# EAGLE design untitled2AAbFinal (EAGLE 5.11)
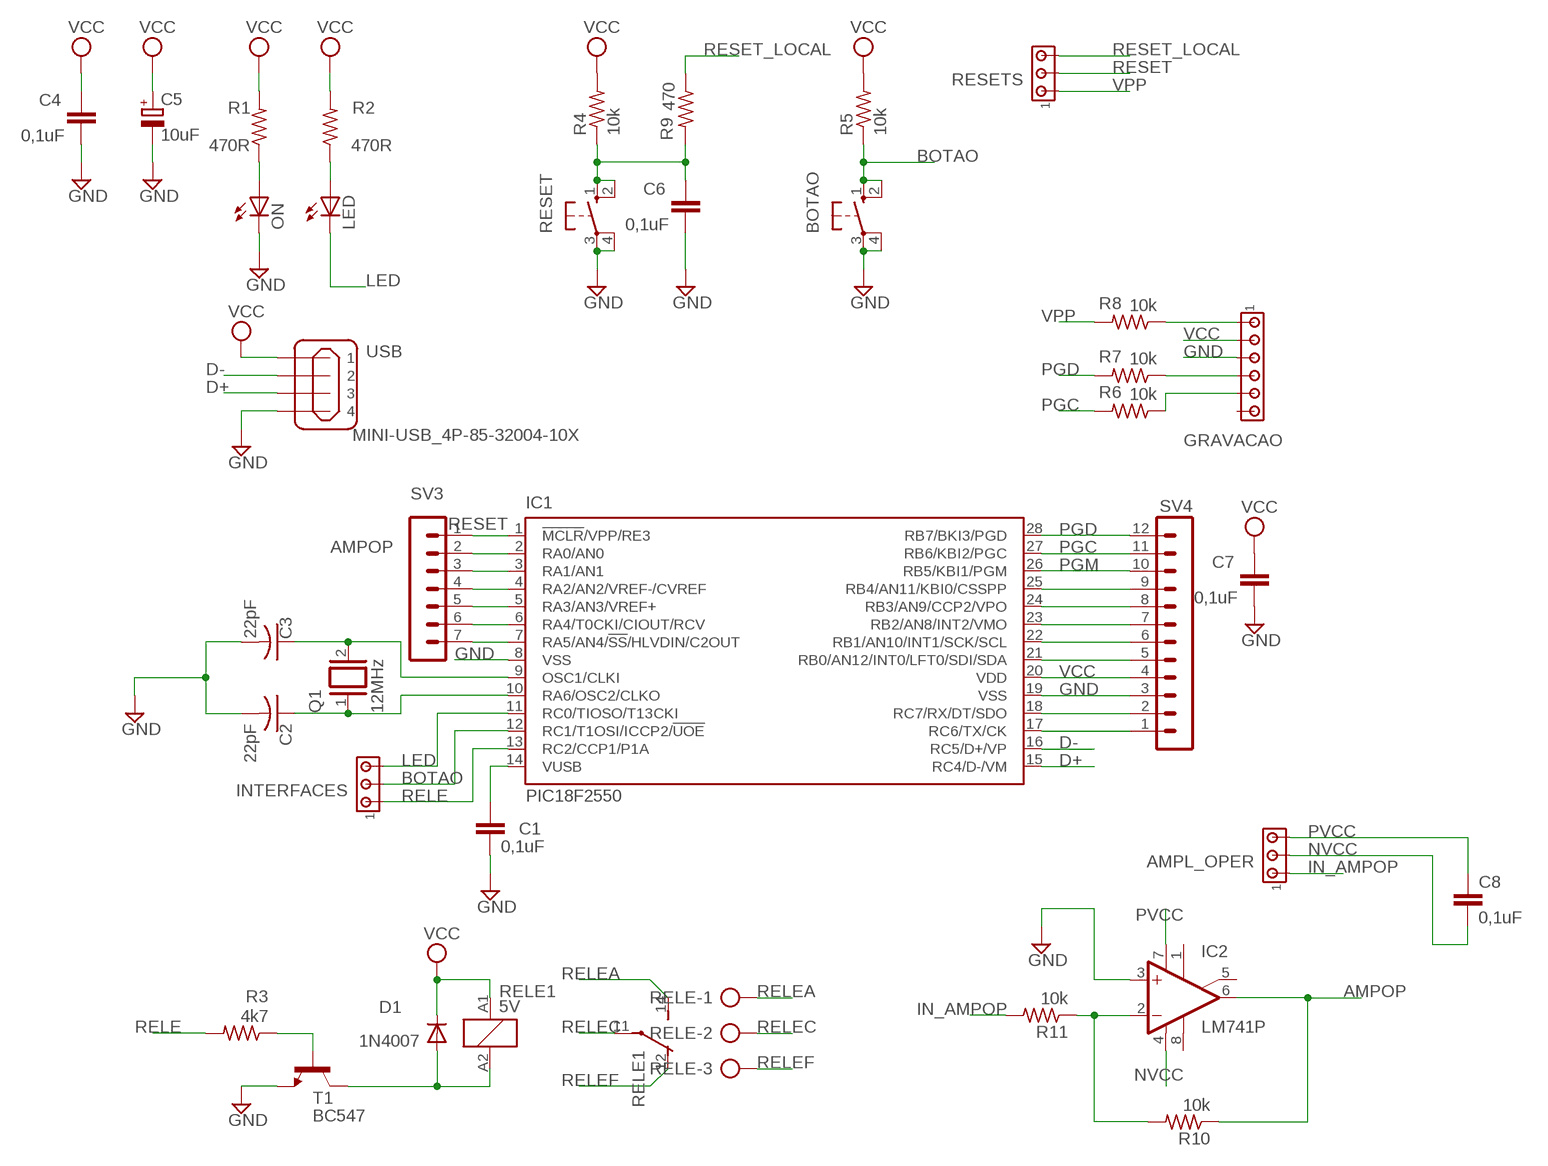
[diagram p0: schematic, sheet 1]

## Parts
AMPL_OPER  MTA03-100  [10X03MTA]
BOTAO  10-XX  [B3F-10XX]
C1  0,1uF  C5/3  [C5B3]
C2  22pF  C-US025-025X050  [C025-025X050]
C3  22pF  C-US025-025X050  [C025-025X050]
C4  0,1uF  C5/3  [C5B3]
C5  10uF  CPOL-EUE5-8.5  [E5-8,5]
C6  0,1uF  C5/3  [C5B3]
C7  0,1uF  C5/3  [C5B3]
C8  0,1uF  C5/3  [C5B3]
D1  1N4007  1N4004  [DO41-10]
GRAVACAO  MTA06-100  [10X06MTA]
IC1  PIC18F2550  PIC18F2550_28DIP  [DIL28-3]
IC2  LM741P  [DIL08]
INTERFACES  MTA03-100  [10X03MTA]
LED  LED5MM  [LED5MM]
ON  LED5MM  [LED5MM]
Q1  12MHz  XTAL/S  [QS]
R1  470R  R-US_0207/10  [0207/10]
R2  470R  R-US_0207/10  [0207/10]
R3  4k7  R-US_0207/10  [0207/10]
R4  10k  R-US_0207/10  [0207/10]
R5  10k  R-US_0207/10  [0207/10]
R6  10k  R-US_0207/10  [0207/10]
R7  10k  R-US_0207/10  [0207/10]
R8  10k  R-US_0207/10  [0207/10]
R9  470  R-US_0207/10  [0207/10]
R10  10k  R-US_0207/10  [0207/10]
R11  10k  R-US_0207/10  [0207/10]
RELE  AK500/3  [AK500/3]
RELE1  5V  ZNS5124  [ZN5]
RESET  10-XX  [B3F-10XX]
RESETS  MTA03-100  [10X03MTA]
SV3  MA07-1  [MA07-1]
SV4  MA12-1  [MA12-1]
T1  BC547  [TO92]
USB  MINI-USB_4P-85-32004-10X  [85-32004-10X]

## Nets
AMPOP: IC1.2(RA0/AN0) IC2.6(OUT) R10.1 SV3.2
BOTAO: BOTAO.1(S) BOTAO.2(S1) IC1.12(RC1/T1OSI/ICCP2/!UOE) INTERFACES.2 R5.1
D+: IC1.15(RC4/D-/VM) USB.3
D-: IC1.16(RC5/D+/VP) USB.2
GND: BOTAO.3(P) BOTAO.4(P1) C1.2 C2.2 C3.2 C4.2 C5.- C6.2 C7.2 GRAVACAO.4 IC1.8(VSS) IC1.19(VSS) IC2.3(+IN) ON.K(C) RESET.3(P) RESET.4(P1) SV4.3 T1.1(E) USB.4
IN_AMPOP: AMPL_OPER.1 R11.2
LED: IC1.11(RC0/TIOSO/T13CKI) INTERFACES.3 LED.K(C)
N$1: C1.1 IC1.14(VUSB)
N$2: D1.A RELE1.A2 T1.3(C)
N$3: LED.A R2.1
N$4: ON.A R1.1
N$5: GRAVACAO.6 R8.1
N$6: IC1.17(RC6/TX/CK) SV4.1
N$7: IC2.2(-IN) R10.2 R11.1
N$8: IC1.18(RC7/RX/DT/SDO) SV4.2
N$9: C3.1 IC1.9(OSC1/CLKI) Q1.2
N$10: C2.1 IC1.10(RA6/OSC2/CLKO) Q1.1
N$12: R3.1 T1.2(B)
N$13: IC1.21(RB0/AN12/INT0/LFT0/SDI/SDA) SV4.5
N$14: IC1.22(RB1/AN10/INT1/SCK/SCL) SV4.6
N$15: IC1.23(RB2/AN8/INT2/VMO) SV4.7
N$16: IC1.24(RB3/AN9/CCP2/VPO) SV4.8
N$17: IC1.25(RB4/AN11/KBI0/CSSPP) SV4.9
N$18: C6.1 R4.1 R9.2 RESET.1(S) RESET.2(S1)
N$19: IC1.3(RA1/AN1) SV3.3
N$20: IC1.4(RA2/AN2/VREF-/CVREF) SV3.4
N$22: IC1.5(RA3/AN3/VREF+) SV3.5
N$23: IC1.6(RA4/T0CKI/CIOUT/RCV) SV3.6
N$24: IC1.7(RA5/AN4/!SS!/HLVDIN/C2OUT) SV3.7
N$25: GRAVACAO.3 R7.1
N$26: GRAVACAO.2 R6.1
NVCC: AMPL_OPER.2 C8.2 IC2.4(V-)
PGC: IC1.27(RB6/KBI2/PGC) R6.2 SV4.11
PGD: IC1.28(RB7/BKI3/PGD) R7.2 SV4.12
PGM: IC1.26(RB5/KBI1/PGM) SV4.10
PVCC: AMPL_OPER.3 C8.1 IC2.7(V+)
RELE: IC1.13(RC2/CCP1/P1A) INTERFACES.1 R3.2
RELEA: RELE1.14(2:S) RELE.1
RELEC: RELE1.11(2:P) RELE.2
RELEF: RELE1.12(2:O) RELE.3
RESET: IC1.1(!MCLR!/VPP/RE3) RESETS.2 SV3.1
RESET_LOCAL: R9.1 RESETS.3
VCC: C4.1 C5.+ C7.1 D1.C GRAVACAO.5 IC1.20(VDD) R1.2 R2.2 R4.2 R5.2 RELE1.A1 SV4.4 USB.1
VPP: R8.2 RESETS.1
Unconnected: GRAVACAO.1 IC2.1(ON1) IC2.5(ON2) IC2.8(OPT)

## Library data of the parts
AMPL_OPER INTERFACES RESETS = con-amp:MTA03-100: AMP connector; OC_FARNELL: unknown; OC_NEWARK: unknown
BOTAO RESET = switch-omron:10-XX: OMRON SWITCH; MPN: B3F-1000; OC_FARNELL: 176432; OC_NEWARK: 36M3542
C1 C4 C6-C8 = capacitor-wima:C: CAPACITOR
C2 C3 = resistor:C-US: CAPACITOR, American symbol
C5 = rcl:CPOL-EU: POLARIZED CAPACITOR, European symbol
D1 = diode:1N4004: DIODE
GRAVACAO = con-amp:MTA06-100: AMP connector; OC_FARNELL: unknown; OC_NEWARK: unknown
IC1 = microchip:PIC18F2*_28: USB Microcontrollers with nanoWatt Technology High-Performance, Enhanced Flash, 28/40/44-Pin, Source: http://ww1.microchip.com/downloads/en/devicedoc/39632c.pdf; MF: MICROCHIP; MPN: PIC18F2550-I/SP; OC_FARNELL: 1523822; OC_NEWARK: 80K6054
IC2 = linear:*741: OP AMP
LED ON = led:LED: LED
Q1 = special:XTAL/S: CRYSTAL
R1-R11 = resistor:R-US_: RESISTOR, American symbol
RELE = con-ptr500:AK500/3: CONNECTOR; OC_FARNELL: unknown; OC_NEWARK: unknown
RELE1 = relay:ZNS5*: Miniature Power PCB Relay SCHRACK 1pole 10 A Source: http://www.schrack.com/.. 5847.pdf; OC_FARNELL: unknown; OC_NEWARK: unknown
SV3 = con-lstb:MA07-1: PIN HEADER; OC_FARNELL: unknown; OC_NEWARK: unknown
SV4 = con-lstb:MA12-1: PIN HEADER; OC_FARNELL: unknown; OC_NEWARK: unknown
T1 = transistor:BC547: NPN TRANSISTOR
USB = con-cypressindustries:MINI-USB_4P-: MINI USB 4 Pol. Source: www.cypressindustries.com; OC_FARNELL: unknown; OC_NEWARK: unknown

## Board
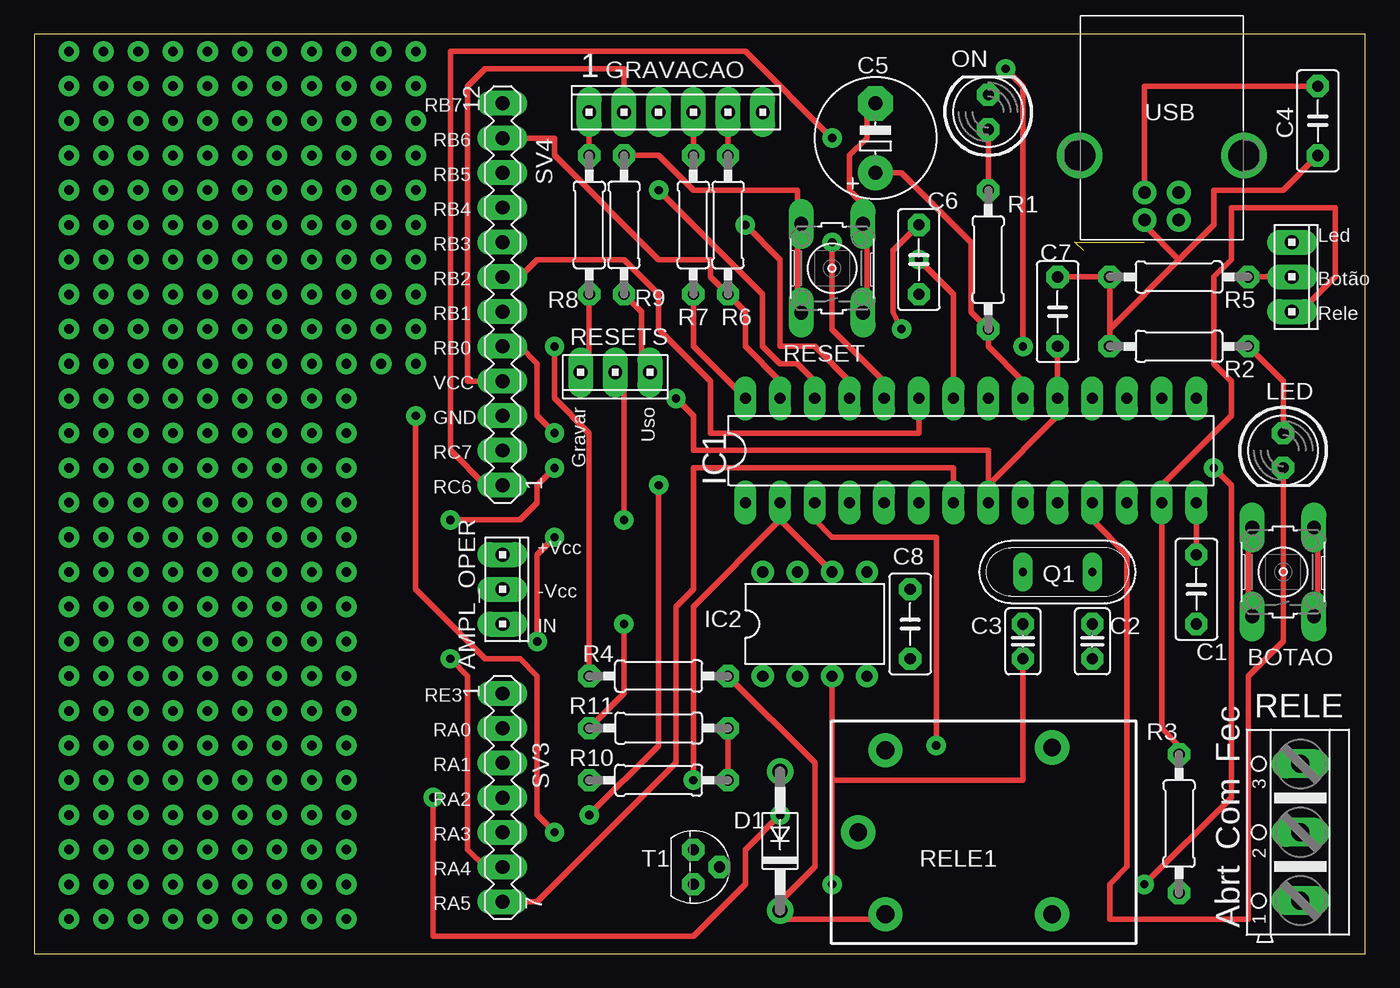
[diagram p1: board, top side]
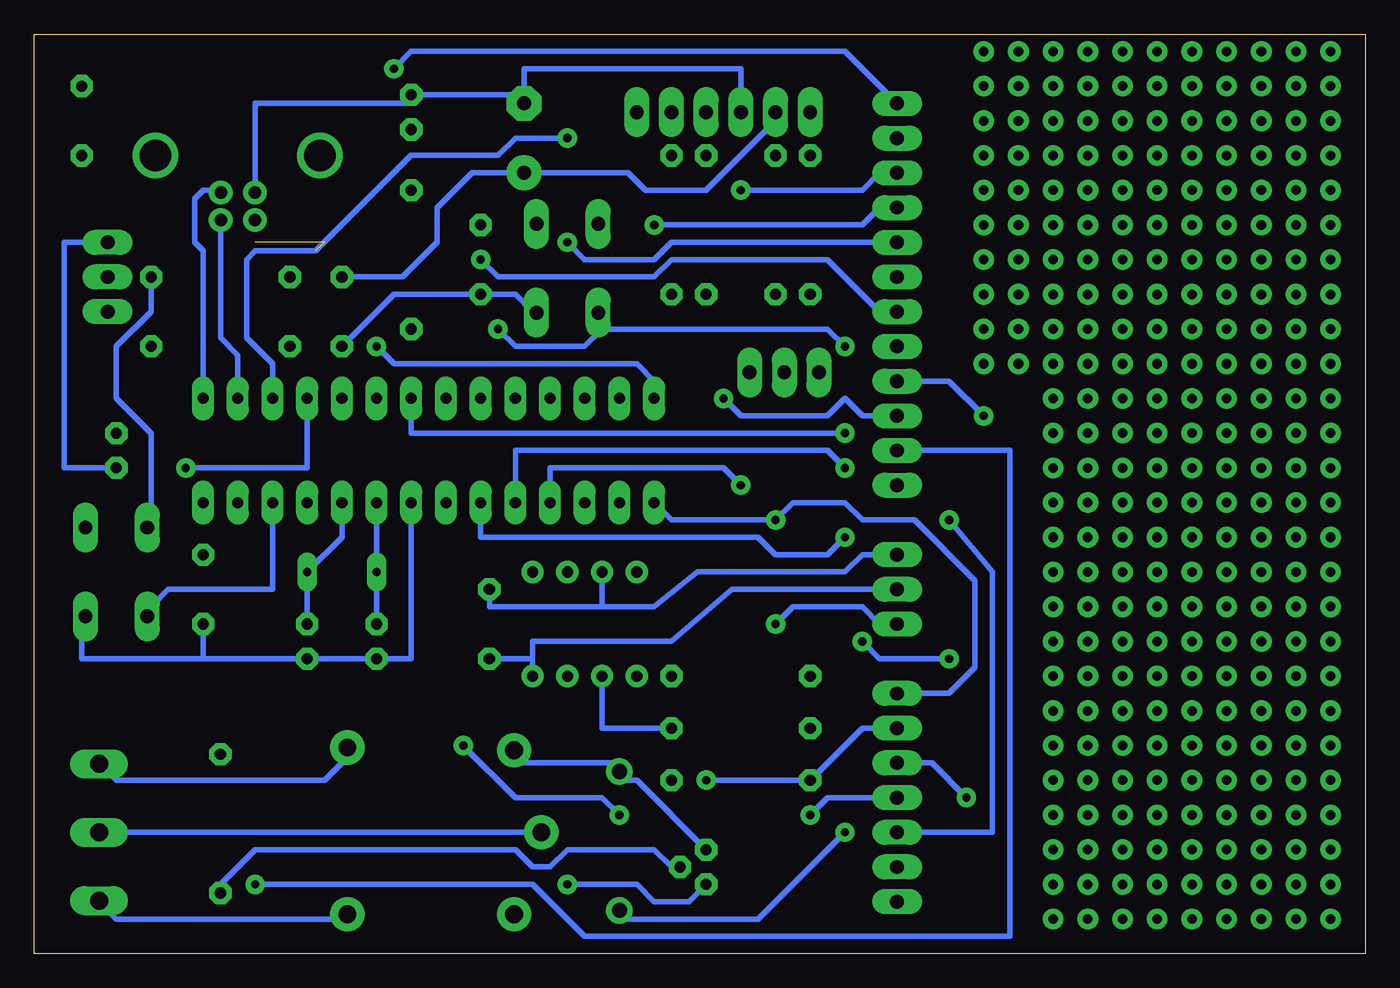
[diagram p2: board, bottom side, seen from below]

Size 97.46 x 67.3 mm. Coordinates in mm from the lower left corner, seen from the top.
Outline: 0,0 97.46,0 97.46,67.3 0,67.3 0,0
Copper layers (1*16): Top 0.035mm / dielectric 1.5mm / Bottom 0.035mm
Design rules "default *": minimum track width 16mil, minimum drill 24mil, track to track 16mil, track to pad 16mil, pad to pad 16mil, via to via 16mil, smd to smd 8mil, copper to edge 40mil, drill to drill 12mil, minimum pad ring 16mil, minimum via ring 16mil, stop-mask expansion 4mil, vias tented up to drill 0mil, thermal gap 10mil

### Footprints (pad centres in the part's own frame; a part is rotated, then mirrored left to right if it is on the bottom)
10X03MTA = drill 1.016 long: 1 2.54,0; 2 0,0; 3 -2.54,0
B3F-10XX = drill 1.016 long: 1 -3.251,2.261; 2 3.251,2.261; 3 -3.251,-2.261; 4 3.251,-2.261
C5B3 = drill 0.813 pad 1.6 octagon: 1 -2.54,0; 2 2.54,0
C025-025X050 = drill 0.813 octagon: 1 -1.27,0; 2 1.27,0
E5-8,5 = drill 1.016 pad 2.54 round: + -2.54,0 | drill 1.016 pad 2.54 octagon: - 2.54,0
DO41-10 = drill 1.118 round: A 5.08,0; C -5.08,0
10X06MTA = drill 1.016 long: 1 6.35,0; 2 3.81,0; 3 1.27,0; 4 -1.27,0; 5 -3.81,0; 6 -6.35,0
DIL28-3 = drill 0.813 long: 1 -16.51,-3.81; 2 -13.97,-3.81; 3 -11.43,-3.81; 4 -8.89,-3.81; 5 -6.35,-3.81; 6 -3.81,-3.81; 7 -1.27,-3.81; 8 1.27,-3.81; 9 3.81,-3.81; 10 6.35,-3.81; 11 8.89,-3.81; 12 11.43,-3.81; 13 13.97,-3.81; 14 16.51,-3.81; 15 16.51,3.81; 16 13.97,3.81; 17 11.43,3.81; 18 8.89,3.81; 19 6.35,3.81; 20 3.81,3.81; 21 1.27,3.81; 22 -1.27,3.81; 23 -3.81,3.81; 24 -6.35,3.81; 25 -8.89,3.81; 26 -11.43,3.81; 27 -13.97,3.81; 28 -16.51,3.81
DIL08 = drill 0.813 pad 1.27 round: 1 -3.81,-3.81; 2 -1.27,-3.81; 3 1.27,-3.81; 4 3.81,-3.81; 5 3.81,3.81; 6 1.27,3.81; 7 -1.27,3.81; 8 -3.81,3.81
LED5MM = drill 0.813 octagon: A -1.27,0; K 1.27,0
QS = drill 0.61 long: 1 -2.54,0; 2 2.54,0
0207/10 = drill 0.813 octagon: 1 -5.08,0; 2 5.08,0
AK500/3 = drill 1.321 long: 1 -5.004,0; 2 0,0; 3 5.004,0
ZN5 = drill 1.3 pad 2.5 round: 11 8.89,0; 12 -5.31,-6.2; 14 -5.31,6; A1 6.89,6; A2 6.89,-6
MA07-1 = drill 1.016 long: 1 -7.62,0; 2 -5.08,0; 3 -2.54,0; 4 0,0; 5 2.54,0; 6 5.08,0; 7 7.62,0
MA12-1 = drill 1.016 long: 1 -13.97,0; 2 -11.43,0; 3 -8.89,0; 4 -6.35,0; 5 -3.81,0; 6 -1.27,0; 7 1.27,0; 8 3.81,0; 9 6.35,0; 10 8.89,0; 11 11.43,0; 12 13.97,0
TO92 = drill 0.813 octagon: 1 1.27,0; 2 0,1.905; 3 -1.27,0
85-32004-10X = drill 0.92 pad 1.27 round: 1 4.71,-1.25; 2 4.71,1.25; 3 2.71,1.25; 4 2.71,-1.25 | drill 2.3 pad 3 round: M1 0,6.02; M2 0,-6.02

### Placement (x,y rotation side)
AMPL_OPER  34.29,26.67 270 top
BOTAO  91.44,27.94 90 top
C1  85.09,26.67 270 top
C2  77.47,22.86 270 top
C3  72.39,22.86 270 top
C4  93.98,60.96 90 top
C5  61.6,59.69 90 top
C6  64.77,50.8 270 top
C7  74.93,46.99 270 top
C8  64.13,24.13 270 top
D1  54.61,8.25 90 top
GRAVACAO  46.99,61.59 0 top
IC1  68.58,36.83 0 top
IC2  57.15,24.13 0 top
INTERFACES  92.07,49.53 270 top
LED  91.44,36.83 270 top
ON  69.85,61.59 90 top
Q1  74.93,27.94 180 top
R1  69.85,50.8 270 top
R2  83.82,44.45 180 top
R3  83.82,9.53 90 top
R4  45.72,20.32 0 top
R5  83.82,49.53 180 top
R6  50.8,53.34 270 top
R7  48.26,53.34 270 top
R8  40.64,53.34 270 top
R9  43.18,53.34 90 top
R10  45.72,12.7 0 top
R11  45.72,16.51 180 top
RELE  92.71,8.89 90 top
RELE1  69.21,8.89 180 top
RESET  58.42,50.17 90 top
RESETS  42.55,42.55 180 top
SV3  34.29,11.43 270 top
SV4  34.29,48.26 90 top
T1  48.26,6.35 270 top
USB  82.55,58.42 270 top

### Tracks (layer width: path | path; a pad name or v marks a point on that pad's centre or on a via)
AMPOP  (via drill 0.61)
  Top 0.406: 54.61,31.75 IC2.6 | 54.61,31.75 48.26,25.4 v48.26,12.7 | 54.61,31.75 IC1.2
  Bottom 0.406: SV3.2 36.83,16.51 R10.1 v48.26,12.7
BOTAO
  Top 0.406: R5.1 INTERFACES.2 | BOTAO.2 88.9,30.48 88.9,25.4 BOTAO.1
  Bottom 0.406: IC1.12 80.01,26.67 87.63,26.67 88.9,25.4 BOTAO.1 | R5.1 88.9,46.99 91.44,44.45 91.44,40.64 88.9,38.1 88.9,31.75 BOTAO.2
D+
  Bottom 0.406: IC1.15 85.09,51.44 85.72,52.07 85.72,55.24 85.09,55.88 83.97,55.88 USB.3
D-
  Bottom 0.406: USB.2 83.82,53.71 83.82,45.08 82.55,43.81 IC1.16
GND  (via drill 0.61)
  Top 0.406: C4.2 81.28,63.5 81.28,55.88 USB.4 | C7.2 IC1.19 74.93,39.37 69.85,34.29 | RESET.3 60.96,46.99 60.96,53.34 RESET.4 60.96,54.61 59.69,55.88 59.69,58.42 60.96,59.69 60.96,62.23 C5.- | 58.42,12.7 IC2.3 | v58.42,5.08 58.42,12.7 | BOTAO.3 93.98,25.4 93.98,30.48 BOTAO.4 | v46.99,40.64 48.26,39.37 48.26,36.83 69.85,36.83 69.85,34.29 | 58.42,12.7 72.39,12.7 C3.2 | IC1.8 69.85,34.29
  Bottom 0.406: GRAVACAO.4 45.72,64.77 61.6,64.77 C5.- 62.23,62.86 ON.K 69.85,62.23 81.28,62.23 81.28,55.88 USB.4 | RESET.3 60.96,46.99 62.23,48.26 C6.2 71.12,48.26 C7.2 | T1.1 49.53,3.81 52.07,3.81 53.34,5.08 v58.42,5.08 | 85.09,21.59 C1.2 | 85.09,21.59 C2.2 C3.2 69.85,21.59 IC1.8 | SV4.3 36.83,39.37 38.1,40.64 39.37,39.37 45.72,39.37 v46.99,40.64 | 85.09,21.59 93.98,21.59 93.98,24.13 BOTAO.3
IN_AMPOP  (via drill 0.61)
  Top 0.406: R11.2 43.18,19.05 v43.18,24.13
  Bottom 0.406: v43.18,24.13 41.91,25.4 36.83,25.4 35.56,24.13 AMPL_OPER.1
LED
  Top 0.406: IC1.11 77.47,31.75 80.01,29.21 80.01,6.35 78.74,5.08 78.74,2.54 88.9,2.54 88.9,20.32 91.44,22.86 LED.K
  Bottom 0.406: LED.K 95.25,35.56 95.25,52.07 INTERFACES.3
N$1
  Top 0.406: C1.1 IC1.14
N$2
  Bottom 0.406: T1.3 53.34,12.7 54.61,12.7 D1.A 54.61,13.97 62.23,13.97 RELE1.A2
N$3
  Top 0.406: R2.1 91.44,41.91 LED.A
N$4
  Top 0.406: R1.1 ON.A
N$5
  Top 0.406: R8.1 GRAVACAO.6
N$6  (via drill 0.61)  (2 unrouted)
  Top 0.406: v58.42,59.69 52.07,66.04 30.48,66.04 30.48,36.83 33.02,34.29 SV4.1
  Bottom 0.406: IC1.17 80.01,43.18 81.91,45.08 81.91,50.8 81.28,51.44 76.83,51.44 69.85,58.42 63.5,58.42 62.23,59.69 v58.42,59.69
N$7
  Top 0.406: R10.2 R11.1
  Bottom 0.406: IC2.2 55.88,16.51 R11.1
N$8  (via drill 0.61)
  Top 0.406: v86.36,35.56 87.63,34.29 87.63,11.43 v81.28,5.08
  Bottom 0.406: IC1.18 77.47,35.56 v86.36,35.56 | v81.28,5.08 60.96,5.08 57.15,1.27 26.04,1.27 26.04,36.83 SV4.2
N$9
  Bottom 0.406: IC1.9 Q1.2 C3.1
N$10
  Bottom 0.406: C2.1 Q1.1 74.93,30.48 IC1.10
N$11  (via drill 0.7)
  other vias: 17.78,43.18
N$12
  Bottom 0.406: R3.1 83.82,5.08 81.28,7.62 62.23,7.62 60.96,6.35 59.69,6.35 58.42,7.62 52.07,7.62 50.8,6.35 T1.2
N$13  (via drill 0.61)
  Top 0.406: v38.1,38.1 36.83,39.37 36.83,43.18 35.56,44.45 SV4.5
  Bottom 0.406: IC1.21 69.85,38.1 v38.1,38.1
N$14  (via drill 0.61)
  Top 0.406: IC1.22 67.31,48.26 v64.77,50.8
  Bottom 0.406: v64.77,50.8 63.5,49.53 52.07,49.53 50.8,50.8 39.37,50.8 35.56,46.99 SV4.6
N$15
  Top 0.406: IC1.23 64.77,38.1 49.53,38.1 49.53,41.91 45.72,45.72 45.72,48.26 43.18,50.8 36.83,50.8 35.56,49.53 SV4.7
N$16  (via drill 0.61)
  Top 0.406: IC1.24 62.23,41.91 58.42,45.72 v58.42,52.07
  Bottom 0.406: v58.42,52.07 57.15,50.8 52.07,50.8 50.8,52.07 SV4.8
N$17  (via drill 0.61)
  Top 0.406: IC1.25 59.69,41.91 57.15,44.45 54.61,44.45 54.61,50.8 v52.07,53.34
  Bottom 0.406: v52.07,53.34 36.83,53.34 35.56,54.61 SV4.9
N$18  (via drill 0.61)
  Top 0.406: R9.2 45.72,58.42 48.26,55.88 55.88,55.88 55.88,54.61 RESET.2 55.88,53.34 55.88,46.99 RESET.1 | R4.1 40.64,38.1 38.1,40.64 v38.1,44.45 | C6.1 62.87,51.44 62.87,46.99 v63.5,45.72
  Bottom 0.406: v38.1,44.45 39.37,45.72 55.88,45.72 | v63.5,45.72 62.23,44.45 57.15,44.45 55.88,45.72 | 55.88,45.72 RESET.1
N$19  (via drill 0.61)
  Top 0.406: IC1.3 57.15,31.75 58.42,30.48 66.04,30.48 v66.04,15.24 | v54.61,10.16 52.07,7.62 52.07,5.08 48.26,1.27 29.21,1.27 v29.21,11.43
  Bottom 0.406: v66.04,15.24 62.23,11.43 55.88,11.43 v54.61,10.16 | v29.21,11.43 31.75,13.97 SV3.3
N$20  (via drill 0.61)
  Top 0.406: v45.72,34.29 45.72,15.24 v40.64,10.16
  Bottom 0.406: IC1.4 59.69,35.56 46.99,35.56 v45.72,34.29 | v40.64,10.16 39.37,11.43 SV3.4
N$21  (via drill 0.7)
  other vias: 17.78,45.72
N$22  (via drill 0.61)
  Top 0.406: v38.1,35.56 36.83,34.29 36.83,33.02 35.56,31.75 v30.48,31.75
  Bottom 0.406: IC1.5 62.23,36.83 39.37,36.83 v38.1,35.56 | v30.48,31.75 27.3,27.94 27.3,8.89 SV3.5
N$23  (via drill 0.61)
  Top 0.406: v38.1,30.48 36.83,29.21 v36.83,22.86 | v30.48,21.59 31.75,20.32 31.75,7.62 33.02,6.35 SV3.6
  Bottom 0.406: IC1.6 64.77,30.48 44.45,30.48 43.18,29.21 39.37,29.21 v38.1,30.48 | v36.83,22.86 35.56,21.59 v30.48,21.59
N$24
  Top 0.406: IC1.7 67.31,35.56 48.26,35.56 48.26,26.67 46.99,25.4 46.99,13.97 36.83,3.81 SV3.7
N$25
  Top 0.406: R7.1 GRAVACAO.3
N$26
  Top 0.406: R6.1 GRAVACAO.2
N$27  (via drill 0.7)
  other vias: 17.78,48.26
N$28  (via drill 0.7)
  other vias: 17.78,50.8
N$29  (via drill 0.7)
  other vias: 17.78,53.34
N$30  (via drill 0.7)
  other vias: 17.78,55.88
N$31  (via drill 0.7)
  other vias: 17.78,58.42
N$32  (via drill 0.7)
  other vias: 17.78,60.96
N$33  (via drill 0.7)
  other vias: 17.78,63.5
N$34  (via drill 0.7)
  other vias: 17.78,66.04
N$35  (via drill 0.7)
  other vias: 20.32,66.04
N$36  (via drill 0.7)
  other vias: 20.32,63.5
N$37  (via drill 0.7)
  other vias: 20.32,60.96
N$38  (via drill 0.7)
  other vias: 20.32,58.42
N$39  (via drill 0.7)
  other vias: 20.32,55.88
N$40  (via drill 0.7)
  other vias: 20.32,53.34
N$41  (via drill 0.7)
  other vias: 20.32,50.8
N$42  (via drill 0.7)
  other vias: 20.32,48.26
N$43  (via drill 0.7)
  other vias: 20.32,45.72
N$44  (via drill 0.7)
  other vias: 20.32,43.18
N$45  (via drill 0.7)
  other vias: 20.32,40.64
N$46  (via drill 0.7)
  other vias: 20.32,38.1
N$47  (via drill 0.7)
  other vias: 20.32,35.56
N$48  (via drill 0.7)
  other vias: 20.32,33.02
N$49  (via drill 0.7)
  other vias: 20.32,30.48
N$50  (via drill 0.7)
  other vias: 20.32,27.94
N$51  (via drill 0.7)
  other vias: 20.32,25.4
N$52  (via drill 0.7)
  other vias: 20.32,22.86
N$53  (via drill 0.7)
  other vias: 20.32,20.32
N$54  (via drill 0.7)
  other vias: 20.32,17.78
N$55  (via drill 0.7)
  other vias: 20.32,15.24
N$56  (via drill 0.7)
  other vias: 20.32,12.7
N$57  (via drill 0.7)
  other vias: 20.32,10.16
N$58  (via drill 0.7)
  other vias: 20.32,7.62
N$59  (via drill 0.7)
  other vias: 20.32,5.08
N$60  (via drill 0.7)
  other vias: 20.32,2.54
N$61  (via drill 0.7)
  other vias: 22.86,2.54
N$62  (via drill 0.7)
  other vias: 22.86,5.08
N$63  (via drill 0.7)
  other vias: 22.86,7.62
N$64  (via drill 0.7)
  other vias: 22.86,10.16
N$65  (via drill 0.7)
  other vias: 22.86,12.7
N$66  (via drill 0.7)
  other vias: 22.86,15.24
N$67  (via drill 0.7)
  other vias: 22.86,17.78
N$68  (via drill 0.7)
  other vias: 22.86,20.32
N$69  (via drill 0.7)
  other vias: 22.86,22.86
N$70  (via drill 0.7)
  other vias: 22.86,25.4
N$71  (via drill 0.7)
  other vias: 22.86,27.94
N$72  (via drill 0.7)
  other vias: 22.86,30.48
N$73  (via drill 0.7)
  other vias: 22.86,33.02
N$74  (via drill 0.7)
  other vias: 22.86,35.56
N$75  (via drill 0.7)
  other vias: 22.86,38.1
N$76  (via drill 0.7)
  other vias: 22.86,40.64
N$77  (via drill 0.7)
  other vias: 22.86,43.18
N$78  (via drill 0.7)
  other vias: 22.86,45.72
N$79  (via drill 0.7)
  other vias: 22.86,48.26
N$80  (via drill 0.7)
  other vias: 22.86,50.8
N$81  (via drill 0.7)
  other vias: 22.86,53.34
N$82  (via drill 0.7)
  other vias: 22.86,55.88
N$83  (via drill 0.7)
  other vias: 22.86,58.42
N$84  (via drill 0.7)
  other vias: 22.86,60.96
N$85  (via drill 0.7)
  other vias: 22.86,63.5
N$86  (via drill 0.7)
  other vias: 22.86,66.04
N$87  (via drill 0.7)
  other vias: 25.4,66.04
N$88  (via drill 0.7)
  other vias: 27.94,66.04
N$89  (via drill 0.7)
  other vias: 27.94,63.5
N$90  (via drill 0.7)
  other vias: 25.4,63.5
N$91  (via drill 0.7)
  other vias: 25.4,60.96
N$92  (via drill 0.7)
  other vias: 27.94,60.96
N$93  (via drill 0.7)
  other vias: 27.94,58.42
N$94  (via drill 0.7)
  other vias: 25.4,58.42
N$95  (via drill 0.7)
  other vias: 25.4,55.88
N$96  (via drill 0.7)
  other vias: 27.94,55.88
N$97  (via drill 0.7)
  other vias: 27.94,53.34
N$98  (via drill 0.7)
  other vias: 17.78,40.64
N$99  (via drill 0.7)
  other vias: 17.78,38.1
N$100  (via drill 0.7)
  other vias: 17.78,35.56
N$101  (via drill 0.7)
  other vias: 17.78,33.02
N$102  (via drill 0.7)
  other vias: 17.78,30.48
N$103  (via drill 0.7)
  other vias: 17.78,27.94
N$104  (via drill 0.7)
  other vias: 17.78,25.4
N$105  (via drill 0.7)
  other vias: 17.78,22.86
N$106  (via drill 0.7)
  other vias: 17.78,20.32
N$107  (via drill 0.7)
  other vias: 17.78,17.78
N$108  (via drill 0.7)
  other vias: 17.78,15.24
N$109  (via drill 0.7)
  other vias: 17.78,12.7
N$110  (via drill 0.7)
  other vias: 17.78,10.16
N$111  (via drill 0.7)
  other vias: 17.78,7.62
N$112  (via drill 0.7)
  other vias: 17.78,5.08
N$113  (via drill 0.7)
  other vias: 17.78,2.54
N$114  (via drill 0.7)
  other vias: 7.62,33.02
N$115  (via drill 0.7)
  other vias: 25.4,53.34
N$116  (via drill 0.7)
  other vias: 25.4,50.8
N$117  (via drill 0.7)
  other vias: 27.94,50.8
N$118  (via drill 0.7)
  other vias: 27.94,48.26
N$119  (via drill 0.7)
  other vias: 25.4,48.26
N$120  (via drill 0.7)
  other vias: 25.4,45.72
N$121  (via drill 0.7)
  other vias: 27.94,45.72
N$122  (via drill 0.7)
  other vias: 27.94,43.18
N$123  (via drill 0.7)
  other vias: 25.4,43.18
N$124  (via drill 0.7)
  other vias: 15.24,66.04
N$125  (via drill 0.7)
  other vias: 15.24,63.5
N$126  (via drill 0.7)
  other vias: 15.24,60.96
N$127  (via drill 0.7)
  other vias: 15.24,55.88
N$128  (via drill 0.7)
  other vias: 15.24,58.42
N$129  (via drill 0.7)
  other vias: 15.24,53.34
N$130  (via drill 0.7)
  other vias: 15.24,50.8
N$131  (via drill 0.7)
  other vias: 15.24,48.26
N$132  (via drill 0.7)
  other vias: 15.24,45.72
N$133  (via drill 0.7)
  other vias: 15.24,43.18
N$134  (via drill 0.7)
  other vias: 15.24,40.64
N$135  (via drill 0.7)
  other vias: 15.24,38.1
N$136  (via drill 0.7)
  other vias: 15.24,35.56
N$137  (via drill 0.7)
  other vias: 15.24,33.02
N$138  (via drill 0.7)
  other vias: 15.24,30.48
N$139  (via drill 0.7)
  other vias: 15.24,27.94
N$140  (via drill 0.7)
  other vias: 15.24,25.4
N$141  (via drill 0.7)
  other vias: 15.24,22.86
N$142  (via drill 0.7)
  other vias: 15.24,20.32
N$143  (via drill 0.7)
  other vias: 15.24,17.78
N$144  (via drill 0.7)
  other vias: 15.24,15.24
N$145  (via drill 0.7)
  other vias: 15.24,12.7
N$146  (via drill 0.7)
  other vias: 15.24,10.16
N$147  (via drill 0.7)
  other vias: 15.24,7.62
N$148  (via drill 0.7)
  other vias: 15.24,5.08
N$149  (via drill 0.7)
  other vias: 15.24,2.54
N$150  (via drill 0.7)
  other vias: 12.7,5.08
N$151  (via drill 0.7)
  other vias: 12.7,2.54
N$152  (via drill 0.7)
  other vias: 12.7,7.62
N$153  (via drill 0.7)
  other vias: 12.7,10.16
N$154  (via drill 0.7)
  other vias: 12.7,12.7
N$155  (via drill 0.7)
  other vias: 12.7,15.24
N$156  (via drill 0.7)
  other vias: 12.7,17.78
N$157  (via drill 0.7)
  other vias: 12.7,20.32
N$158  (via drill 0.7)
  other vias: 12.7,22.86
N$159  (via drill 0.7)
  other vias: 12.7,25.4
N$160  (via drill 0.7)
  other vias: 12.7,27.94
N$161  (via drill 0.7)
  other vias: 12.7,30.48
N$162  (via drill 0.7)
  other vias: 12.7,33.02
N$163  (via drill 0.7)
  other vias: 12.7,35.56
N$164  (via drill 0.7)
  other vias: 12.7,38.1
N$165  (via drill 0.7)
  other vias: 12.7,40.64
N$166  (via drill 0.7)
  other vias: 12.7,43.18
N$167  (via drill 0.7)
  other vias: 12.7,45.72
N$168  (via drill 0.7)
  other vias: 12.7,48.26
N$169  (via drill 0.7)
  other vias: 12.7,50.8
N$170  (via drill 0.7)
  other vias: 12.7,53.34
N$171  (via drill 0.7)
  other vias: 12.7,55.88
N$172  (via drill 0.7)
  other vias: 12.7,58.42
N$173  (via drill 0.7)
  other vias: 12.7,60.96
N$174  (via drill 0.7)
  other vias: 12.7,63.5
N$175  (via drill 0.7)
  other vias: 12.7,66.04
N$176  (via drill 0.7)
  other vias: 10.16,66.04
N$177  (via drill 0.7)
  other vias: 10.16,63.5
N$178  (via drill 0.7)
  other vias: 10.16,60.96
N$179  (via drill 0.7)
  other vias: 10.16,58.42
N$180  (via drill 0.7)
  other vias: 10.16,55.88
N$181  (via drill 0.7)
  other vias: 10.16,53.34
N$182  (via drill 0.7)
  other vias: 10.16,50.8
N$183  (via drill 0.7)
  other vias: 10.16,48.26
N$184  (via drill 0.7)
  other vias: 10.16,45.72
N$185  (via drill 0.7)
  other vias: 10.16,43.18
N$186  (via drill 0.7)
  other vias: 10.16,40.64
N$187  (via drill 0.7)
  other vias: 10.16,38.1
N$188  (via drill 0.7)
  other vias: 10.16,35.56
N$189  (via drill 0.7)
  other vias: 10.16,33.02
N$190  (via drill 0.7)
  other vias: 10.16,30.48
N$191  (via drill 0.7)
  other vias: 10.16,27.94
N$192  (via drill 0.7)
  other vias: 10.16,25.4
N$193  (via drill 0.7)
  other vias: 10.16,22.86
N$194  (via drill 0.7)
  other vias: 10.16,20.32
N$195  (via drill 0.7)
  other vias: 10.16,17.78
N$196  (via drill 0.7)
  other vias: 10.16,15.24
N$197  (via drill 0.7)
  other vias: 10.16,12.7
N$198  (via drill 0.7)
  other vias: 10.16,10.16
N$199  (via drill 0.7)
  other vias: 10.16,7.62
N$200  (via drill 0.7)
  other vias: 10.16,5.08
N$201  (via drill 0.7)
  other vias: 10.16,2.54
N$202  (via drill 0.7)
  other vias: 7.62,2.54
N$203  (via drill 0.7)
  other vias: 5.08,2.54
N$204  (via drill 0.7)
  other vias: 2.54,2.54
N$205  (via drill 0.7)
  other vias: 2.54,5.08
N$206  (via drill 0.7)
  other vias: 2.54,7.62
N$207  (via drill 0.7)
  other vias: 2.54,12.7
N$208  (via drill 0.7)
  other vias: 2.54,10.16
N$209  (via drill 0.7)
  other vias: 2.54,15.24
N$210  (via drill 0.7)
  other vias: 2.54,17.78
N$211  (via drill 0.7)
  other vias: 2.54,22.86
N$212  (via drill 0.7)
  other vias: 2.54,20.32
N$213  (via drill 0.7)
  other vias: 2.54,25.4
N$214  (via drill 0.7)
  other vias: 2.54,27.94
N$215  (via drill 0.7)
  other vias: 2.54,33.02
N$216  (via drill 0.7)
  other vias: 2.54,30.48
N$217  (via drill 0.7)
  other vias: 2.54,35.56
N$218  (via drill 0.7)
  other vias: 2.54,38.1
N$219  (via drill 0.7)
  other vias: 2.54,40.64
N$220  (via drill 0.7)
  other vias: 2.54,43.18
N$221  (via drill 0.7)
  other vias: 2.54,45.72
N$222  (via drill 0.7)
  other vias: 2.54,48.26
N$223  (via drill 0.7)
  other vias: 2.54,50.8
N$224  (via drill 0.7)
  other vias: 5.08,53.34
N$225  (via drill 0.7)
  other vias: 2.54,53.34
N$226  (via drill 0.7)
  other vias: 2.54,55.88
N$227  (via drill 0.7)
  other vias: 2.54,58.42
N$228  (via drill 0.7)
  other vias: 2.54,60.96
N$229  (via drill 0.7)
  other vias: 2.54,63.5
N$230  (via drill 0.7)
  other vias: 2.54,66.04
N$231  (via drill 0.7)
  other vias: 5.08,66.04
N$232  (via drill 0.7)
  other vias: 5.08,63.5
N$233  (via drill 0.7)
  other vias: 5.08,60.96
N$234  (via drill 0.7)
  other vias: 5.08,58.42
N$235  (via drill 0.7)
  other vias: 5.08,55.88
N$236  (via drill 0.7)
  other vias: 7.62,55.88
N$237  (via drill 0.7)
  other vias: 7.62,58.42
N$238  (via drill 0.7)
  other vias: 7.62,60.96
N$239  (via drill 0.7)
  other vias: 7.62,63.5
N$240  (via drill 0.7)
  other vias: 7.62,66.04
N$241  (via drill 0.7)
  other vias: 7.62,53.34
N$242  (via drill 0.7)
  other vias: 7.62,48.26
N$243  (via drill 0.7)
  other vias: 7.62,50.8
N$244  (via drill 0.7)
  other vias: 7.62,45.72
N$245  (via drill 0.7)
  other vias: 7.62,43.18
N$246  (via drill 0.7)
  other vias: 7.62,40.64
N$247  (via drill 0.7)
  other vias: 7.62,38.1
N$248  (via drill 0.7)
  other vias: 7.62,35.56
N$249  (via drill 0.7)
  other vias: 5.08,35.56
N$250  (via drill 0.7)
  other vias: 5.08,38.1
N$251  (via drill 0.7)
  other vias: 5.08,40.64
N$252  (via drill 0.7)
  other vias: 5.08,43.18
N$253  (via drill 0.7)
  other vias: 5.08,45.72
N$254  (via drill 0.7)
  other vias: 5.08,48.26
N$255  (via drill 0.7)
  other vias: 5.08,50.8
N$256  (via drill 0.7)
  other vias: 5.08,33.02
N$257  (via drill 0.7)
  other vias: 5.08,30.48
N$258  (via drill 0.7)
  other vias: 5.08,27.94
N$259  (via drill 0.7)
  other vias: 5.08,25.4
N$260  (via drill 0.7)
  other vias: 5.08,22.86
N$261  (via drill 0.7)
  other vias: 5.08,20.32
N$262  (via drill 0.7)
  other vias: 5.08,17.78
N$263  (via drill 0.7)
  other vias: 5.08,15.24
N$264  (via drill 0.7)
  other vias: 5.08,12.7
N$265  (via drill 0.7)
  other vias: 5.08,10.16
N$266  (via drill 0.7)
  other vias: 5.08,7.62
N$267  (via drill 0.7)
  other vias: 5.08,5.08
N$268  (via drill 0.7)
  other vias: 7.62,7.62
N$269  (via drill 0.7)
  other vias: 7.62,5.08
N$270  (via drill 0.7)
  other vias: 7.62,10.16
N$271  (via drill 0.7)
  other vias: 7.62,12.7
N$272  (via drill 0.7)
  other vias: 7.62,15.24
N$273  (via drill 0.7)
  other vias: 7.62,17.78
N$274  (via drill 0.7)
  other vias: 7.62,20.32
N$275  (via drill 0.7)
  other vias: 7.62,22.86
N$276  (via drill 0.7)
  other vias: 7.62,25.4
N$277  (via drill 0.7)
  other vias: 7.62,27.94
N$278  (via drill 0.7)
  other vias: 7.62,30.48
NVCC
  Bottom 0.406: 60.96,21.59 C8.2 | AMPL_OPER.2 46.36,26.67 50.8,22.86 60.96,22.86 60.96,21.59 | 60.96,21.59 IC2.4
PGC
  Top 0.406: IC1.27 54.61,41.91 52.07,44.45 52.07,46.99 R6.2 49.53,49.53 49.53,50.8 45.72,50.8 38.1,58.42 38.1,59.69 SV4.11
PGD  (via drill 0.61)
  Top 0.406: IC1.28 48.26,44.45 R7.2 | v71.12,64.77 72.39,63.5 v72.39,44.45
  Bottom 0.406: SV4.12 38.1,66.04 69.85,66.04 v71.12,64.77 | v72.39,44.45 71.12,43.18 53.34,43.18 52.07,41.91 IC1.28
PGM  (via drill 0.61)
  Top 0.406: IC1.26 57.15,41.91 55.88,43.18 54.61,43.18 53.34,44.45 53.34,48.26 v45.72,55.88
  Bottom 0.406: v45.72,55.88 36.83,55.88 35.56,57.15 SV4.10
PVCC
  Bottom 0.406: 55.88,25.4 IC2.7 | 55.88,25.4 64.13,25.4 C8.1 | AMPL_OPER.3 36.83,29.21 38.1,27.94 48.9,27.94 52.07,25.4 55.88,25.4
RELE
  Top 0.406: R3.2 83.82,15.24 82.55,16.51 IC1.13 82.55,34.29 87.63,39.37 87.63,41.91 86.36,43.18 86.36,49.53 87.63,50.8 87.63,54.61 95.25,54.61 95.25,49.53 92.71,46.99 INTERFACES.1
RELEA
  Bottom 0.406: RELE.1 92.71,3.81 91.44,2.54 74.93,2.54 RELE1.14
RELEC
  Bottom 0.406: RELE1.11 RELE.2
RELEF
  Bottom 0.406: RELE.3 92.71,13.97 91.44,12.7 76.2,12.7 74.93,13.97 RELE1.12
RESET  (via drill 0.61)
  Top 0.406: v43.18,31.75 43.18,41.91 RESETS.2
  Bottom 0.406: IC1.1 50.8,31.75 v43.18,31.75 41.91,33.02 38.1,33.02 36.83,31.75 33.02,31.75 28.57,27.31 28.57,20.96 30.48,19.05 SV3.1
RESET_LOCAL
  Top 0.406: R9.1 44.45,46.99 44.45,43.18 RESETS.3
VCC  (via drill 0.61)
  Top 0.406: R4.2 57.15,13.97 57.15,6.35 54.61,3.81 D1.C 54.61,2.54 62.23,2.54 RELE1.A1 | SV4.4 31.75,41.91 31.75,63.5 33.02,64.77 43.18,64.77 GRAVACAO.5 | IC1.20 72.39,41.91 69.85,44.45 R1.2 68.58,46.99 68.58,52.07 63.5,57.15 C5.+ | 78.74,45.72 R5.2 C7.1 | 78.74,45.72 R2.2 | C4.1 91.44,55.88 86.36,55.88 86.36,53.34 83.82,50.8 | 78.74,45.72 83.82,50.8 | 83.82,50.8 81.28,53.34 USB.1 | v38.1,8.89 36.83,10.16 36.83,20.32 35.56,21.59 33.02,21.59 27.94,26.67 v27.94,39.37
  Bottom 0.406: GRAVACAO.5 43.18,60.96 48.26,55.88 52.7,55.88 53.98,57.15 C5.+ 65.4,57.15 67.94,54.61 67.94,52.07 70.48,49.53 C7.1 | v38.1,8.89 44.45,2.54 54.61,2.54 D1.C | v27.94,39.37 30.48,41.91 SV4.4
VPP
  Top 0.406: R8.2 40.64,43.18 RESETS.1

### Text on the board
tNames: 1 | RB7 | RB6 | RB5 | RB4 | Led | RB3 | RB2 | Botão | RB1 | Rele | RB0 | VCC | Gravar | Uso | GND | RC7 | RC6 | +Vcc | -Vcc | IN | RE3 | RA0 | Fec | RA1 | RA2 | RA3 | Com | RA4 | RA5 | Abrt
